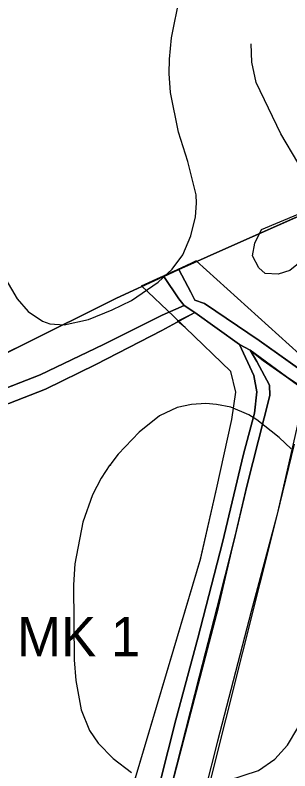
# Model space of a CAD drawing. Extents: x -662620 to -656370, y -1067090 to -1062990.
# Drawn here: x -661439.8 to -661307.5, y -1063853.7 to -1063489.7 of the extents above; entities that cross this region are included whole.
import ezdxf

# ---------------------------------------------------------------- set-up
doc = ezdxf.new("R2010")
doc.units = 0
for name, color, linetype in [('HRANICE_KATASTRÁLNÍHO_ÚZEMÍ', 7, 'Continuous'), ('LOKÁLNÍ_BIOKORIDOR_-_NAVRŽENÝ', 7, 'Continuous'), ('OBVOD_PÚ', 7, 'Continuous'), ('ORNÁ_PŮDA_-_STÁVAJÍCÍ', 7, 'Continuous'), ('OSTATNÍ_PLOCHA_-_STÁVAJÍCÍ', 7, 'Continuous'), ('Popis_-_Lokální_biocentrum_-_navržené', 7, 'Continuous'), ('TRVALÝ_TRÁVNÍ_POROST_-_NAVRŽENÝ', 7, 'Continuous'), ('VODNÍ_PLOCHA_-_STÁVAJÍCÍ', 7, 'Continuous'), ('VRSTEVNICE_ZÁKLADNÍ', 7, 'Continuous')]:
    doc.layers.add(name, color=color, linetype=linetype)

msp = doc.modelspace()

# ---------------------------------------------------------------- linework, layer by layer
at = {"layer": 'HRANICE_KATASTRÁLNÍHO_ÚZEMÍ'}
msp.add_lwpolyline([(-661047.41, -1063551.36), (-661060.01, -1063554.04), (-661162.23, -1063545.87), (-661175.96, -1063543.41), (-661179.52, -1063542.76), (-661196.06, -1063548.52), (-661296.48, -1063583.47), (-661339.88, -1063602.81), (-661361.03, -1063612.18), (-661368.76, -1063615.8), (-661390.99, -1063625.94), (-661393.94, -1063627.39), (-661474.55, -1063667.56)], dxfattribs=at)
at = {"layer": 'LOKÁLNÍ_BIOKORIDOR_-_NAVRŽENÝ'}
for points in [[(-661398.32, -1063912.59), (-661350.52, -1063751.74), (-661342.8, -1063718.06), (-661335.43, -1063684.45), (-661333.51, -1063671.24), (-661335.99, -1063661.26), (-661357.93, -1063640.17), (-661363.38, -1063634.92), (-661378.88, -1063620.02), (-661369.88, -1063615.93), (-661367.9, -1063615.03), (-661367.88, -1063615.02), (-661367.87, -1063615.01), (-661367.75, -1063614.96), (-661367.71, -1063614.94), (-661367.68, -1063614.93), (-661367.64, -1063614.91), (-661367.63, -1063614.9), (-661367.6, -1063614.89), (-661367.58, -1063614.89), (-661367.56, -1063614.87), (-661367.48, -1063614.84), (-661367.42, -1063614.81), (-661367.4, -1063614.8), (-661367.33, -1063614.77), (-661367.31, -1063614.76), (-661367.3, -1063614.75), (-661367.27, -1063614.74), (-661366.98, -1063614.61), (-661366.89, -1063614.57), (-661366.87, -1063614.56), (-661366.85, -1063614.55), (-661366.82, -1063614.54), (-661366.39, -1063614.34), (-661366.26, -1063614.28), (-661366.25, -1063614.28), (-661366.22, -1063614.27), (-661366.2, -1063614.26), (-661366.19, -1063614.25), (-661366.17, -1063614.25), (-661366.14, -1063614.23), (-661366.08, -1063614.2), (-661366.06, -1063614.19), (-661366.02, -1063614.17), (-661365.97, -1063614.15), (-661365.94, -1063614.14), (-661365.92, -1063614.13), (-661365.79, -1063614.07), (-661365.77, -1063614.06), (-661365.75, -1063614.05), (-661365.73, -1063614.04), (-661365.71, -1063614.04), (-661365.61, -1063613.99), (-661365.41, -1063613.9), (-661365.4, -1063613.89), (-661365.38, -1063613.89), (-661365.37, -1063613.88), (-661365.34, -1063613.87), (-661365.31, -1063613.85), (-661365.3, -1063613.85), (-661365.25, -1063613.82), (-661365.22, -1063613.81), (-661365.2, -1063613.8), (-661365.17, -1063613.79), (-661365.14, -1063613.78), (-661365.1, -1063613.76), (-661365.08, -1063613.75), (-661365.06, -1063613.74), (-661365.05, -1063613.73), (-661365.02, -1063613.72), (-661365.01, -1063613.72), (-661364.98, -1063613.7), (-661364.94, -1063613.69), (-661364.92, -1063613.68), (-661364.91, -1063613.67), (-661364.64, -1063613.55), (-661364.62, -1063613.54), (-661364.26, -1063613.38), (-661364.03, -1063613.27), (-661363.99, -1063613.25), (-661363.96, -1063613.24), (-661363.94, -1063613.23), (-661363.92, -1063613.22), (-661363.91, -1063613.22), (-661363.9, -1063613.21), (-661363.88, -1063613.2), (-661363.86, -1063613.19), (-661363.84, -1063613.19), (-661363.83, -1063613.18), (-661363.79, -1063613.16), (-661352.64, -1063608.1), (-661302.98, -1063653.06)], [(-661305.55, -1063696.4), (-661313.86, -1063730.62), (-661326.22, -1063776.91), (-661342.36, -1063839.32), (-661354.22, -1063886.28)]]:
    msp.add_lwpolyline(points, dxfattribs=at)
at = {"layer": 'OBVOD_PÚ'}
for points in [[(-661296.48, -1063583.47), (-661339.88, -1063602.81)], [(-661339.88, -1063602.81), (-661361.03, -1063612.18)], [(-661361.03, -1063612.18), (-661368.76, -1063615.8)], [(-661368.76, -1063615.8), (-661390.99, -1063625.94)], [(-661393.94, -1063627.39), (-661474.55, -1063667.56)], [(-661390.99, -1063625.94), (-661393.94, -1063627.39)]]:
    msp.add_lwpolyline(points, dxfattribs=at)
at = {"layer": 'ORNÁ_PŮDA_-_STÁVAJÍCÍ'}
for p, q in [((-661339.88, -1063602.81), (-661296.48, -1063583.47)), ((-661361.03, -1063612.18), (-661339.88, -1063602.81)), ((-661361.06, -1063612.2), (-661361.03, -1063612.18)), ((-661355.23, -1063623.16), (-661361.06, -1063612.2)), ((-661353.23, -1063627.02), (-661355.23, -1063623.16)), ((-661348.68, -1063628.57), (-661353.23, -1063627.02)), ((-661322.27, -1063646.38), (-661348.68, -1063628.57)), ((-661369.19, -1063641.54), (-661353.29, -1063632.95)), ((-661353.29, -1063632.95), (-661331.82, -1063648.37)), ((-661400.94, -1063657.93), (-661369.19, -1063641.54)), ((-661331.82, -1063648.37), (-661324.97, -1063663.2)), ((-661303.59, -1063659.74), (-661322.27, -1063646.38)), ((-661323.5, -1063656.55), (-661326.66, -1063651.09)), ((-661326.66, -1063651.09), (-661322.58, -1063654.21)), ((-661317.33, -1063667.96), (-661323.5, -1063656.55)), ((-661322.58, -1063654.21), (-661319.91, -1063656.08)), ((-661319.91, -1063656.08), (-661309.24, -1063663.96)), ((-661425.23, -1063669.79), (-661400.94, -1063657.93)), ((-661324.97, -1063663.2), (-661323.5, -1063671.14)), ((-661309.24, -1063663.96), (-661300.8, -1063669.49)), ((-661442.78, -1063676.79), (-661425.23, -1063669.79)), ((-661323.5, -1063671.14), (-661324.61, -1063681.33)), ((-661317.27, -1063672.85), (-661317.33, -1063667.96)), ((-661328.1, -1063715.89), (-661317.27, -1063672.85)), ((-661324.61, -1063681.33), (-661329.81, -1063701.13)), ((-661329.81, -1063701.13), (-661340.02, -1063743.77)), ((-661331.09, -1063729.39), (-661328.1, -1063715.89)), ((-661334.65, -1063743.78), (-661331.09, -1063729.39)), ((-661340.02, -1063743.77), (-661351.88, -1063789.7)), ((-661342.6, -1063774.93), (-661334.65, -1063743.78)), ((-661351.05, -1063808.06), (-661342.6, -1063774.93)), ((-661351.88, -1063789.7), (-661362.44, -1063829.13)), ((-661368.35, -1063876.17), (-661351.05, -1063808.06)), ((-661362.44, -1063829.13), (-661366.05, -1063843.69)), ((-661366.05, -1063843.69), (-661374.7, -1063877.52))]:
    msp.add_line(p, q, dxfattribs=at)
for points in [[(-661303.59, -1063659.74), (-661322.27, -1063646.38), (-661348.68, -1063628.57), (-661353.23, -1063627.02), (-661355.23, -1063623.16), (-661361.06, -1063612.2), (-661361.03, -1063612.18), (-661339.88, -1063602.81), (-661296.48, -1063583.47)], [(-661442.78, -1063676.79), (-661425.23, -1063669.79), (-661400.94, -1063657.93), (-661369.19, -1063641.54), (-661353.29, -1063632.95), (-661331.82, -1063648.37), (-661324.97, -1063663.2), (-661323.5, -1063671.14), (-661324.61, -1063681.33), (-661329.81, -1063701.13), (-661340.02, -1063743.77), (-661351.88, -1063789.7), (-661362.44, -1063829.13), (-661366.05, -1063843.69), (-661374.7, -1063877.52), (-661393.15, -1063946.95), (-661396.3, -1063959.29), (-661401.23, -1063959.39), (-661400.48, -1063952.31), (-661396.36, -1063913.97), (-661405.8, -1063903.48), (-661430.25, -1063892.05), (-661447.11, -1063869.86)], [(-661368.35, -1063876.17), (-661351.05, -1063808.06), (-661342.6, -1063774.93), (-661334.65, -1063743.78), (-661331.09, -1063729.39), (-661328.1, -1063715.89), (-661317.27, -1063672.85), (-661317.33, -1063667.96), (-661323.5, -1063656.55), (-661326.66, -1063651.09), (-661322.58, -1063654.21), (-661319.91, -1063656.08), (-661309.24, -1063663.96), (-661300.8, -1063669.49)]]:
    msp.add_lwpolyline(points, dxfattribs=at)
at = {"layer": 'OSTATNÍ_PLOCHA_-_STÁVAJÍCÍ'}
for p, q in [((-661390.99, -1063625.94), (-661368.76, -1063615.8)), ((-661390.99, -1063625.94), (-661368.76, -1063615.8)), ((-661368.76, -1063615.8), (-661368.18, -1063615.53)), ((-661368.76, -1063615.8), (-661368.18, -1063615.53)), ((-661368.18, -1063615.53), (-661360.96, -1063626.32)), ((-661368.18, -1063615.53), (-661360.96, -1063626.32)), ((-661474.55, -1063667.56), (-661393.94, -1063627.39)), ((-661474.55, -1063667.56), (-661393.94, -1063627.39)), ((-661393.94, -1063627.39), (-661390.99, -1063625.94)), ((-661393.94, -1063627.39), (-661390.99, -1063625.94)), ((-661360.96, -1063626.32), (-661358.43, -1063629.62)), ((-661360.96, -1063626.32), (-661358.43, -1063629.62)), ((-661358.43, -1063629.62), (-661368.94, -1063634.26)), ((-661358.43, -1063629.62), (-661368.94, -1063634.26)), ((-661368.94, -1063634.26), (-661397.31, -1063648.34)), ((-661368.94, -1063634.26), (-661397.31, -1063648.34)), ((-661397.31, -1063648.34), (-661427.8, -1063662.91)), ((-661397.31, -1063648.34), (-661427.8, -1063662.91)), ((-661427.8, -1063662.91), (-661459.95, -1063675.44)), ((-661427.8, -1063662.91), (-661459.95, -1063675.44))]:
    msp.add_line(p, q, dxfattribs=at)
msp.add_lwpolyline([(-661368.18, -1063615.53), (-661360.96, -1063626.32), (-661358.43, -1063629.62), (-661368.94, -1063634.26), (-661397.31, -1063648.34), (-661427.8, -1063662.91), (-661459.95, -1063675.44), (-661487.6, -1063683.98), (-661501.33, -1063688.29), (-661524.16, -1063693), (-661533.62, -1063694.6), (-661552.53, -1063699.17), (-661565.47, -1063701.92), (-661566.13, -1063699.96), (-661474.55, -1063667.56), (-661393.94, -1063627.39), (-661390.99, -1063625.94), (-661368.76, -1063615.8)], close=True, dxfattribs=at)
msp.add_lwpolyline([(-661368.18, -1063615.53), (-661360.96, -1063626.32), (-661358.43, -1063629.62), (-661368.94, -1063634.26), (-661397.31, -1063648.34), (-661427.8, -1063662.91), (-661459.95, -1063675.44), (-661487.6, -1063683.98), (-661501.33, -1063688.29), (-661524.16, -1063693), (-661533.62, -1063694.6), (-661552.53, -1063699.17), (-661565.47, -1063701.92), (-661566.13, -1063699.96), (-661474.55, -1063667.56), (-661393.94, -1063627.39), (-661390.99, -1063625.94), (-661368.76, -1063615.8)], close=True, dxfattribs=at)
at = {"layer": 'TRVALÝ_TRÁVNÍ_POROST_-_NAVRŽENÝ'}
msp.add_lwpolyline([(-661361.06, -1063612.2), (-661355.23, -1063623.16), (-661353.23, -1063627.02), (-661348.68, -1063628.57), (-661322.28, -1063646.38), (-661303.59, -1063659.74), (-661300.86, -1063660.75), (-661302.98, -1063653.06), (-661352.64, -1063608.1), (-661361.03, -1063612.18)], dxfattribs=at)
for points in [[(-661357.93, -1063640.17), (-661361.61, -1063637.03), (-661353.29, -1063632.95), (-661331.82, -1063648.37), (-661324.97, -1063663.2), (-661323.5, -1063671.14), (-661324.61, -1063681.33), (-661329.81, -1063701.13), (-661340.02, -1063743.77), (-661351.88, -1063789.7), (-661362.44, -1063829.13), (-661366.05, -1063843.69), (-661374.7, -1063877.52), (-661393.15, -1063946.95), (-661396.89, -1063958.85), (-661401.23, -1063959.39), (-661400.48, -1063952.31), (-661396.63, -1063914.27), (-661398.32, -1063912.59), (-661350.44, -1063751.3), (-661342.8, -1063718.06), (-661335.43, -1063684.45), (-661333.51, -1063671.24), (-661335.99, -1063661.26)], [(-661326.66, -1063651.09), (-661320.33, -1063655.97), (-661309.24, -1063663.96), (-661300.32, -1063670.4), (-661302.75, -1063682.09), (-661313.86, -1063730.62), (-661363.23, -1063927.47), (-661373.85, -1063959.23), (-661388.66, -1063959.12), (-661368.35, -1063876.18), (-661341.86, -1063775.07), (-661328.1, -1063715.89), (-661317.27, -1063672.85), (-661317.33, -1063667.96), (-661323.5, -1063656.55)]]:
    msp.add_lwpolyline(points, close=True, dxfattribs=at)
at = {"layer": 'VODNÍ_PLOCHA_-_STÁVAJÍCÍ'}
for p, q in [((-661368.18, -1063615.53), (-661361.06, -1063612.2)), ((-661361.06, -1063612.2), (-661355.23, -1063623.16)), ((-661360.96, -1063626.32), (-661368.18, -1063615.53)), ((-661355.23, -1063623.16), (-661353.23, -1063627.02)), ((-661358.43, -1063629.62), (-661360.96, -1063626.32)), ((-661353.23, -1063627.02), (-661348.68, -1063628.57)), ((-661368.94, -1063634.26), (-661358.43, -1063629.62)), ((-661358.43, -1063629.62), (-661353.29, -1063632.95)), ((-661353.29, -1063632.95), (-661358.43, -1063629.62)), ((-661348.68, -1063628.57), (-661322.28, -1063646.38)), ((-661397.31, -1063648.34), (-661368.94, -1063634.26)), ((-661353.29, -1063632.95), (-661369.19, -1063641.54)), ((-661331.82, -1063648.37), (-661353.29, -1063632.95)), ((-661369.19, -1063641.54), (-661400.94, -1063657.93)), ((-661427.8, -1063662.91), (-661397.31, -1063648.34)), ((-661324.97, -1063663.2), (-661331.82, -1063648.37)), ((-661331.82, -1063648.37), (-661326.67, -1063651.09)), ((-661326.67, -1063651.09), (-661331.82, -1063648.37)), ((-661322.28, -1063646.38), (-661296.68, -1063664.69)), ((-661326.67, -1063651.09), (-661323.5, -1063656.55)), ((-661309.24, -1063663.96), (-661326.67, -1063651.09)), ((-661323.5, -1063656.55), (-661317.33, -1063667.96)), ((-661400.94, -1063657.93), (-661425.23, -1063669.79)), ((-661459.95, -1063675.44), (-661427.8, -1063662.91)), ((-661323.5, -1063671.14), (-661324.97, -1063663.2)), ((-661300.8, -1063669.5), (-661309.24, -1063663.96)), ((-661425.23, -1063669.79), (-661442.78, -1063676.79)), ((-661324.61, -1063681.33), (-661323.5, -1063671.14)), ((-661317.33, -1063667.96), (-661317.27, -1063672.85)), ((-661317.27, -1063672.85), (-661328.1, -1063715.89)), ((-661329.81, -1063701.13), (-661324.61, -1063681.33)), ((-661340.02, -1063743.77), (-661329.81, -1063701.13)), ((-661328.1, -1063715.89), (-661334.65, -1063743.77)), ((-661351.88, -1063789.7), (-661340.02, -1063743.77)), ((-661334.65, -1063743.77), (-661351.05, -1063808.06)), ((-661362.44, -1063829.13), (-661351.88, -1063789.7)), ((-661351.05, -1063808.06), (-661368.35, -1063876.18)), ((-661366.05, -1063843.69), (-661362.44, -1063829.13)), ((-661374.7, -1063877.52), (-661366.05, -1063843.69))]:
    msp.add_line(p, q, dxfattribs=at)
msp.add_lwpolyline([(-661300.8, -1063669.5), (-661309.24, -1063663.96), (-661326.67, -1063651.09), (-661331.82, -1063648.37), (-661353.29, -1063632.95), (-661358.43, -1063629.62), (-661360.96, -1063626.32), (-661368.18, -1063615.53), (-661361.06, -1063612.2), (-661355.23, -1063623.16), (-661353.23, -1063627.02), (-661348.68, -1063628.57), (-661322.28, -1063646.38), (-661296.68, -1063664.69)], dxfattribs=at)
for points in [[(-661557.6, -1063710.06), (-661562.64, -1063710.99), (-661564.5, -1063705.5), (-661564.64, -1063704.39), (-661565.47, -1063701.92), (-661552.53, -1063699.17), (-661533.62, -1063694.6), (-661524.16, -1063693), (-661501.33, -1063688.29), (-661487.6, -1063683.98), (-661459.95, -1063675.44), (-661427.8, -1063662.91), (-661397.31, -1063648.34), (-661368.94, -1063634.26), (-661358.43, -1063629.62), (-661353.29, -1063632.95), (-661369.19, -1063641.54), (-661400.94, -1063657.93), (-661425.23, -1063669.79), (-661442.78, -1063676.79), (-661482.07, -1063689.85), (-661505.92, -1063696.68), (-661530.34, -1063701.72)], [(-661386.28, -1063950.59), (-661388.68, -1063959.12), (-661396.3, -1063959.29), (-661393.15, -1063946.95), (-661374.7, -1063877.52), (-661366.05, -1063843.69), (-661362.44, -1063829.13), (-661351.88, -1063789.7), (-661340.02, -1063743.77), (-661329.81, -1063701.13), (-661324.61, -1063681.33), (-661323.5, -1063671.14), (-661324.97, -1063663.2), (-661331.82, -1063648.37), (-661326.67, -1063651.09), (-661323.5, -1063656.55), (-661317.33, -1063667.96), (-661317.27, -1063672.85), (-661328.1, -1063715.89), (-661334.65, -1063743.77), (-661351.05, -1063808.06), (-661368.35, -1063876.18)]]:
    msp.add_lwpolyline(points, close=True, dxfattribs=at)
at = {"layer": 'VRSTEVNICE_ZÁKLADNÍ'}
for points in [[(-661445.91, -1063614.37), (-661438.75, -1063626.41), (-661433.44, -1063632.43), (-661426.56, -1063637.16), (-661423.12, -1063638.45), (-661416.24, -1063638.88), (-661404.48, -1063636.3), (-661393.02, -1063631.57), (-661383.84, -1063627.13), (-661370.94, -1063618.38), (-661364.2, -1063612.08), (-661359.04, -1063605.2), (-661355.17, -1063596.02), (-661353.02, -1063586.85), (-661352.45, -1063580.25), (-661352.59, -1063576.24), (-661356.6, -1063560.18), (-661361.19, -1063546.13), (-661365.06, -1063526.92), (-661365.64, -1063517.75), (-661365.49, -1063510.87), (-661364.49, -1063500.55), (-661360.47, -1063480.48)], [(-661445.91, -1063614.37), (-661438.75, -1063626.41), (-661433.44, -1063632.43), (-661426.56, -1063637.16), (-661423.12, -1063638.45), (-661416.24, -1063638.88), (-661404.48, -1063636.3), (-661393.02, -1063631.57), (-661383.84, -1063627.13), (-661370.94, -1063618.38), (-661364.2, -1063612.08), (-661359.04, -1063605.2), (-661355.17, -1063596.02), (-661353.02, -1063586.85), (-661352.45, -1063580.25), (-661352.59, -1063576.24), (-661356.6, -1063560.18), (-661361.19, -1063546.13), (-661365.06, -1063526.92), (-661365.64, -1063517.75), (-661365.49, -1063510.87), (-661364.49, -1063500.55), (-661360.47, -1063480.48)], [(-661303.69, -1063560.6), (-661311.91, -1063546.91), (-661323.74, -1063522.18), (-661325.82, -1063512.41), (-661326.19, -1063503.49)], [(-661295.18, -1063602.72), (-661307.61, -1063612.67), (-661313.17, -1063614.45), (-661319.46, -1063614.12), (-661322.49, -1063611.45), (-661325.53, -1063605.68), (-661324.42, -1063599.46), (-661321.23, -1063592.91), (-661303.62, -1063585.51)], [(-661306.86, -1063698.66), (-661312.74, -1063693.07), (-661323.49, -1063684.61), (-661327.36, -1063682.18), (-661335.96, -1063678.59), (-661342.84, -1063677.16), (-661348, -1063676.73), (-661354.88, -1063677.16), (-661361.77, -1063678.74), (-661370.37, -1063682.61), (-661380.11, -1063690.63), (-661390.15, -1063701.1), (-661393.73, -1063705.83), (-661394.02, -1063706.83), (-661394.16, -1063706.26), (-661398.32, -1063712.71), (-661402.48, -1063720.74), (-661407.21, -1063733.93), (-661411.08, -1063754), (-661411.65, -1063764.03), (-661411.36, -1063800.16), (-661410.5, -1063810.19), (-661407.92, -1063824.24), (-661403.91, -1063834.28), (-661399.75, -1063840.3), (-661392.59, -1063847.75), (-661383.84, -1063854.49)], [(-661306.86, -1063698.66), (-661312.74, -1063693.07), (-661323.49, -1063684.61), (-661327.36, -1063682.18), (-661335.96, -1063678.59), (-661342.84, -1063677.16), (-661348, -1063676.73), (-661354.88, -1063677.16), (-661361.77, -1063678.74), (-661370.37, -1063682.61), (-661380.11, -1063690.63), (-661390.15, -1063701.1), (-661393.73, -1063705.83), (-661394.02, -1063706.83), (-661394.16, -1063706.26), (-661398.32, -1063712.71), (-661402.48, -1063720.74), (-661407.21, -1063733.93), (-661411.08, -1063754), (-661411.65, -1063764.03), (-661411.36, -1063800.16), (-661410.5, -1063810.19), (-661407.92, -1063824.24), (-661403.91, -1063834.28), (-661399.75, -1063840.3), (-661392.59, -1063847.75), (-661383.84, -1063854.49)], [(-661337.39, -1063858.36), (-661322.69, -1063853.46), (-661314.74, -1063848.04), (-661308.72, -1063841.3), (-661303.71, -1063832.99)], [(-661337.39, -1063858.36), (-661322.69, -1063853.46), (-661314.74, -1063848.04), (-661308.72, -1063841.3), (-661303.71, -1063832.99)]]:
    msp.add_lwpolyline(points, dxfattribs=at)

# ---------------------------------------------------------------- texts
at = {"layer": 'Popis_-_Lokální_biocentrum_-_navržené'}
msp.add_text('MK 1', height=19, dxfattribs=at).set_placement((-661438.86, -1063798.51))

doc.saveas('drawing.dxf')
